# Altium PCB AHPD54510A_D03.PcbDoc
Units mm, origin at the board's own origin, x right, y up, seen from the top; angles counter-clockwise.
Board outline 70.4 x 70.4 mm, 2 copper layers (Top Layer, Bottom Layer), stack 1.57 mm thick; 18 components, 11 nets, 73 pads, 316 vias.
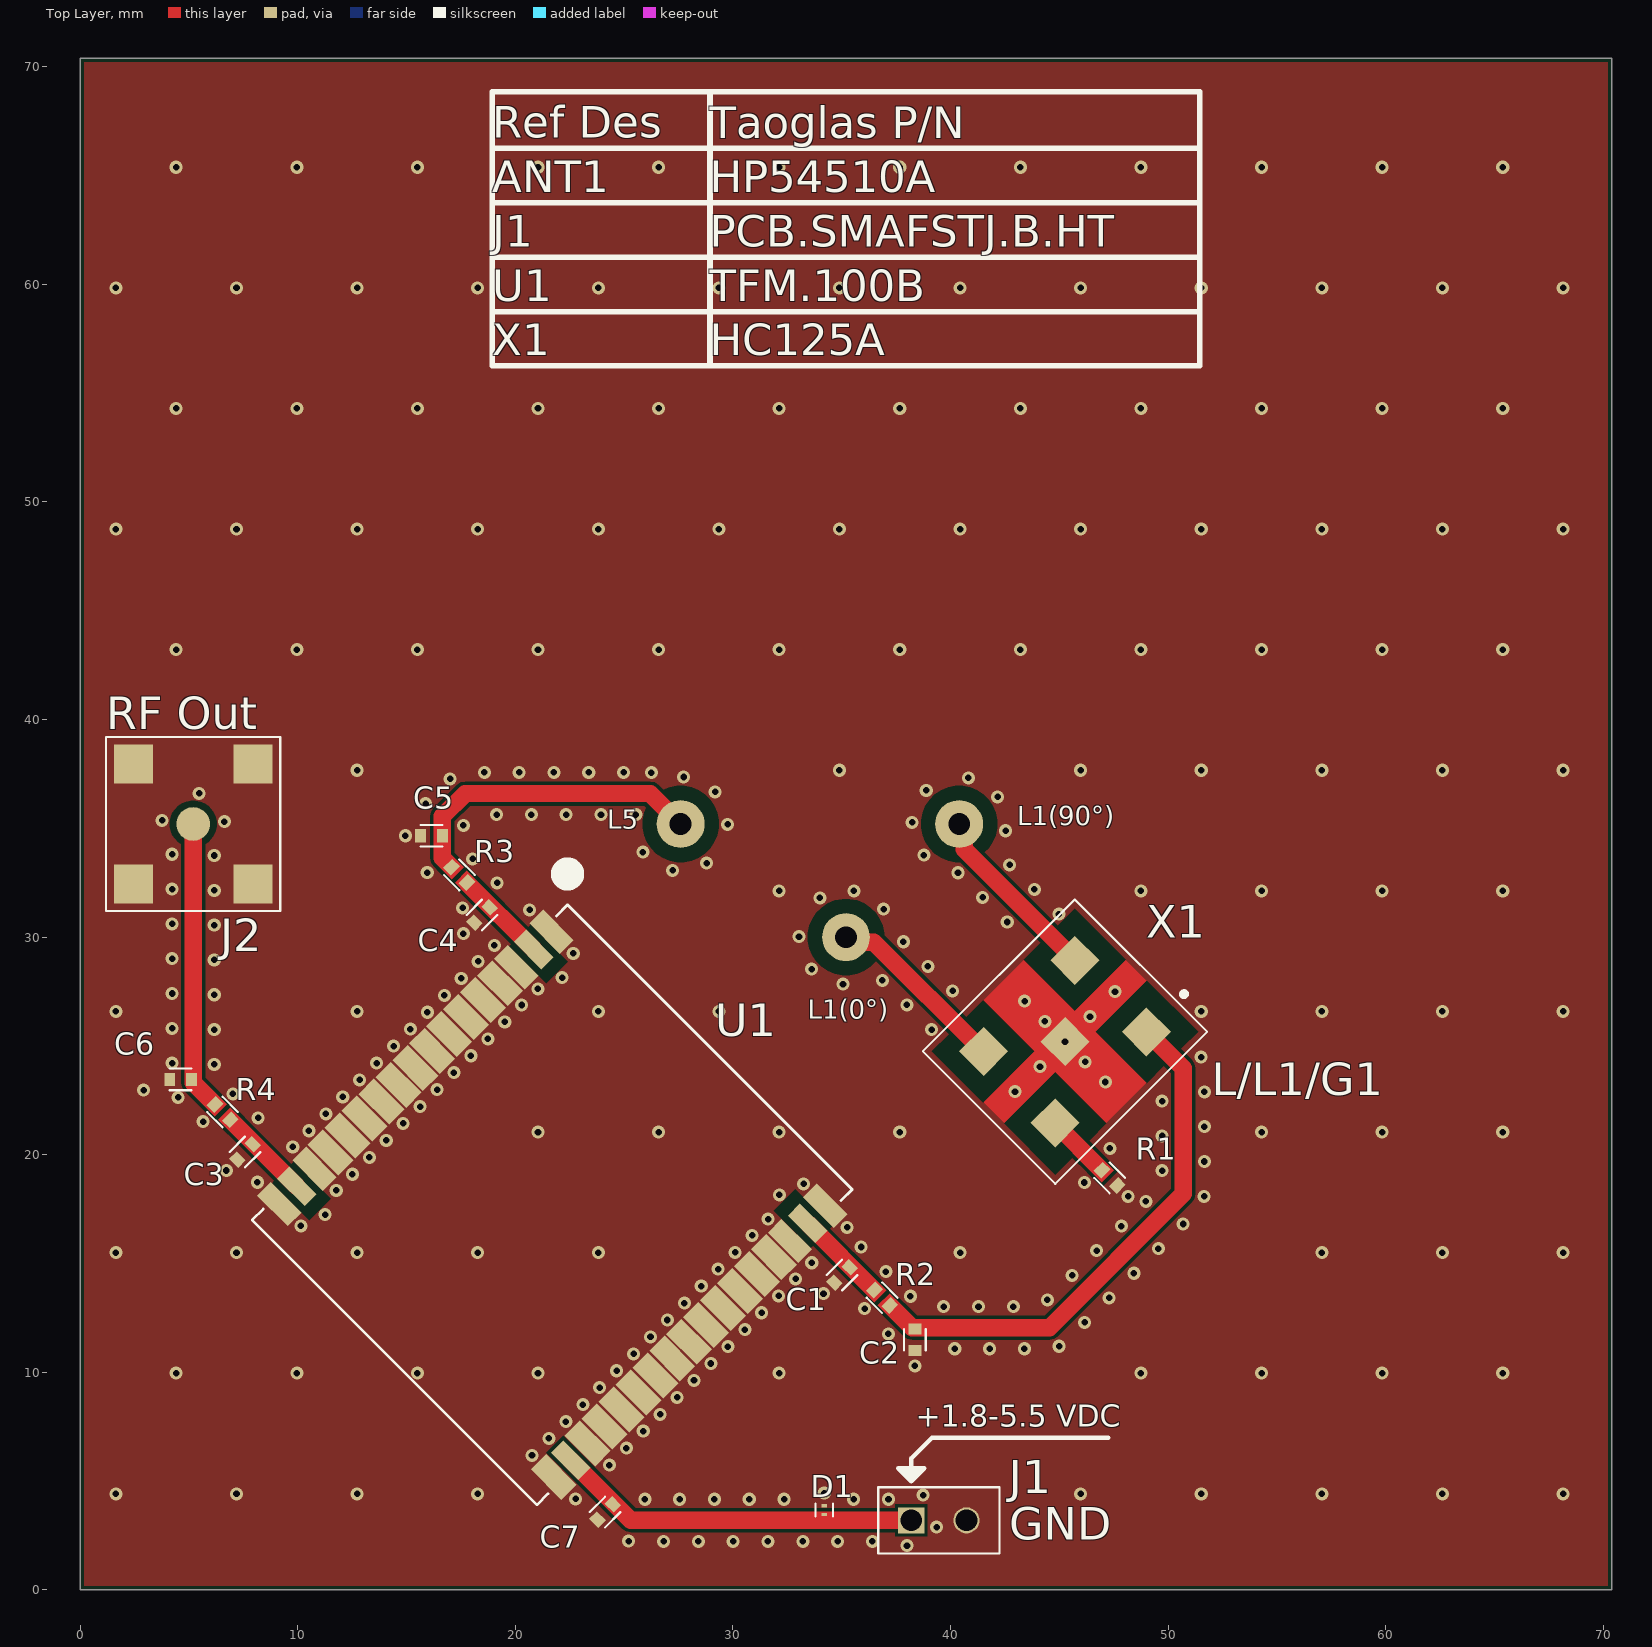
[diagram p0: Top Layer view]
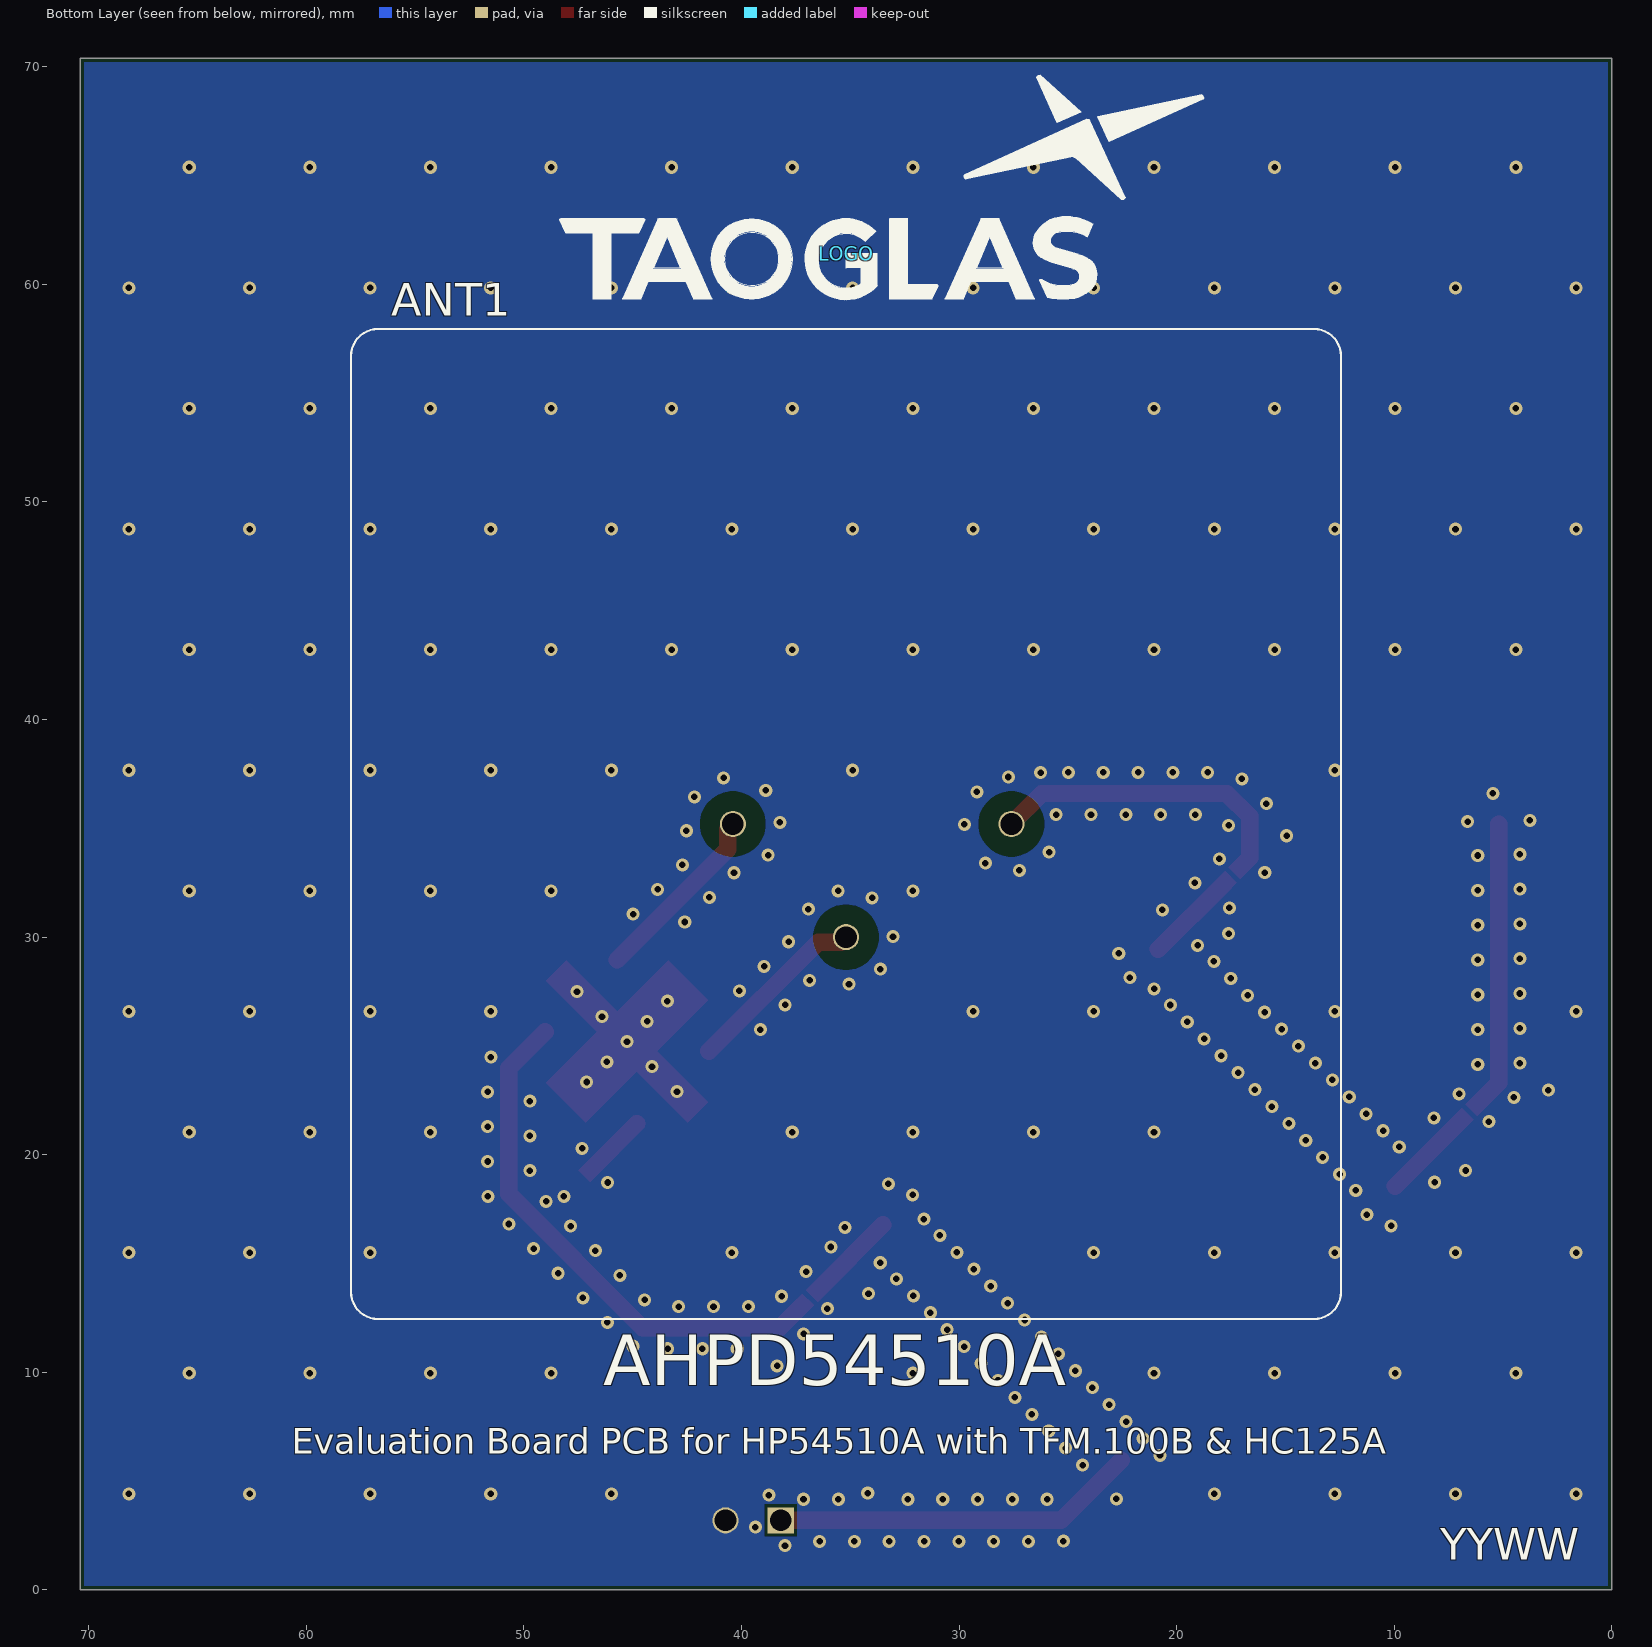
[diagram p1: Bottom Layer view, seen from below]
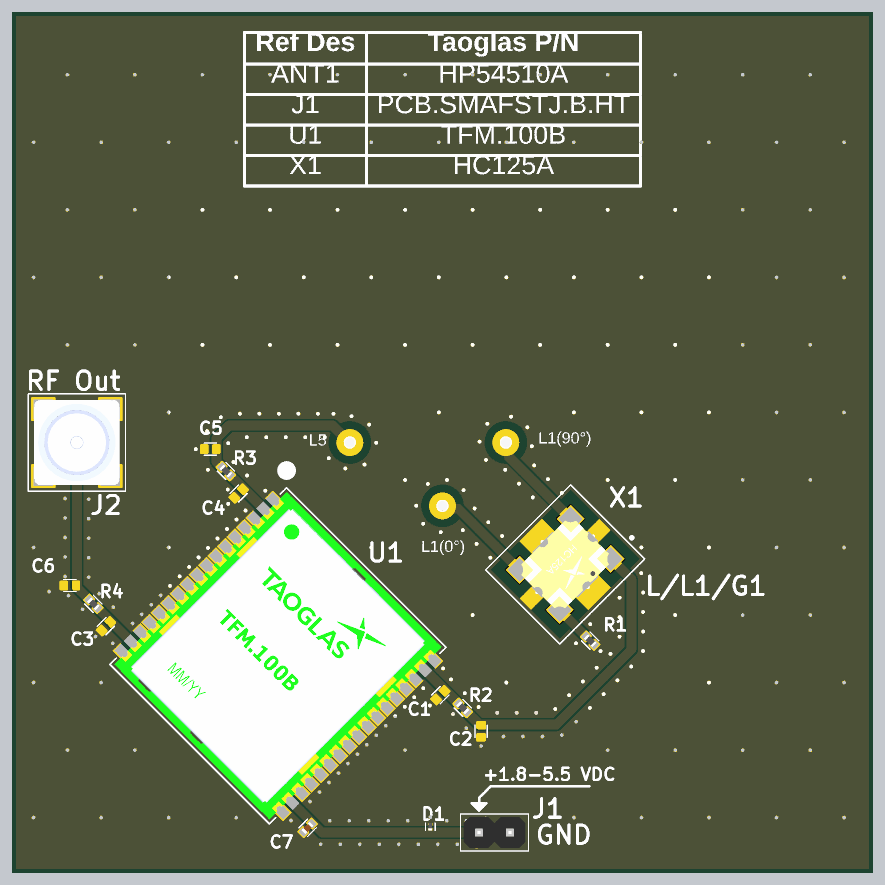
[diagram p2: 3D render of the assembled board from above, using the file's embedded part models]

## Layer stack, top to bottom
Top Solder Mask: solder mask 0.01, Solder Resist, Dk 3.5
Top Layer: signal copper 0.035
Dielectric: core 1.5, FR-4, Dk 4.2
Bottom Layer: signal copper 0.035
Bottom Solder Mask: solder mask 0.01, Solder Resist, Dk 3.5

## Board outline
0,0 70.4,0 70.4,70.4 0,70.4

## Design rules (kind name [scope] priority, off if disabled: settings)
BoardOutlineClearance [All] p1: gap=0.196 ignorepadtopadclearanceinfootprint=FALSE
Clearance Clearance_Polygon [All] p1: gap=0.14 ignorepadtopadclearanceinfootprint=FALSE except(0.05: Arc-Arc Arc-Track Track-Track; 0.1: Arc-SMDPad Arc-THPad Track-SMDPad Track-THPad SMDPad-SMDPad SMDPad-THPad THPad-THPad; 0.2: Arc-Via Arc-Text Arc-Hole Track-Via Track-Text Track-Hole SMDPad-Via SMDPad-Text SMDPad-Hole THPad-Via THPad-Text THPad-Hole Via-Via Via-Text Via-Hole Fill-Text Fill-Hole Poly-Text Poly-Hole Region-Text Region-Hole Text-Text Text-Hole)
HoleSize [All] p1: absolutevalues=TRUE maxlimit=6 minlimit=0.15 maxpercent=80.000 minpercent=20.000
MinimumAnnularRing [All] p1: minimumring=0.1
MinimumSolderMaskSliver [All vs InPadClass('All Pads')] p1: minsoldermaskwidth=0.05
PolygonConnect [All] p1: connectstyle=Direct reliefconductorwidth=0.254 reliefentries=4 polygonreliefangle="90 Angle" airgapwidth=0.254
RoutingVias [All] p1: holewidth=0.3 width=0.8 viastyle="Through Hole" minholewidth=0.15 minwidth=0.65 maxholewidth=6 maxwidth=6.5
SilkToSilkClearance [All] p1: silktosilkclearance=0.1
SilkToSolderMaskClearance [IsPad or IsVia vs OnLayer('Top Overlay')] p1: minsilkscreentomaskgap=0.05 clearancetoexposedcopper=FALSE
SilkToSolderMaskClearance SilkToSolderMaskClearance_1 [IsPad or IsVia vs OnLayer('Bottom Overlay')] p2: minsilkscreentomaskgap=0.05 clearancetoexposedcopper=FALSE
SolderMaskExpansion [Not IsVia] p1: expansion=0.1 istentingtop=FALSE
Width [All] p1: maxlimit=5 minlimit=0.1 preferedwidth=1 minimp=50.000000 maximp=50.000000 favimp=50.000000
26 further rules are at their usual default settings.

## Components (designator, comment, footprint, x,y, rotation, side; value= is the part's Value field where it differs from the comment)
ANT1 "TAOGLAS_HP54510A" TAOGLAS_HP54510A 35.2,35.2 r180 bottom
C1 "DNF" "0402 - DNF" 35.019,14.473 r225 top
C2 "DNF" "0402 - DNF" 38.368,11.499 r90 top
C3 "DNF" "0402 - DNF" 7.583,20.13 r45 top
C4 "DNF" "0402 - DNF" 18.473,31.019 r45 top
C5 "DNF" "0402 - DNF" 16.15,34.66 r180 top
C6 "DNF" "0402 - DNF" 4.623,23.467 r180 top
C7 "Capacitor_Ceramic_1005(0402)_L1_W0.5_H0.5mm_100pF+-5%_50V_-55 to 125C_Murata_GRM1555C1H101JA01" "Capacitor - 0402 - GRM" 24.13,3.583 r45 top value=100pF
D1 "ESD245B1W0201E6327XTSA1" "Diode - 0201 (0603 Metric) - DSN0603-2" 34.2,3.67 r90 top
J1 "PREC002SAAN-RC" SULLINS_PREC002SAAN-RC 39.47,3.2 r0 top
J2 "TAOGLAS_PCB.SMAFSTJ.B.HT" TAOGLAS_PCB.SMAFSTJ.B.HT 5.2,35.2 r90 top
LOGO "TAOGLAS_LOGO" "TAOGLAS_LOGO - No R - 10.3mm" 35.2,61.4 r180 bottom
R1 "Resistor_Thick Film_1005(0402)_49.9Ohms+-1%_0.1W" "Resistor - 0402 - ERJ-2RK" 47.315,18.937 r315 top value=49.9
R2 "Resistor_Thick Film_1005(0402)_0Ohm" "Resistor - 0402 - RC_L" 36.861,13.428 r315 top value=0
R3 "Resistor_Thick Film_1005(0402)_0Ohm" "Resistor - 0402 - RC_L" 17.428,32.861 r135 top value=0
R4 "Resistor_Thick Film_1005(0402)_0Ohm" "Resistor - 0402 - RC_L" 6.552,21.959 r315 top value=0
U1 "TAOGLAS_TFM.100B" TAOGLAS_TFM.100B 21.7,17.7 r315 top
X1 "TAOGLAS_HC125A" TAOGLAS_HC125A 45.264,25.2 r225 top

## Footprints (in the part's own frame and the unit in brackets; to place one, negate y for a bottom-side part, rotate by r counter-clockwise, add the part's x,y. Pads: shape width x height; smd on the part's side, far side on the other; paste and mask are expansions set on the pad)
"0402 - DNF" [mm]
  rect 0.5x0.6 smd paste-2539.97 mask+0.1: 1(-0.5,0) 2(0.5,0)
  silkscreen extent -0.5,-0.5 0.5,0.5
"Capacitor - 0402 - GRM" [mm]
  rect 0.5x0.6 smd mask+0.1: 1(-0.5,0) 2(0.5,0)
  silkscreen extent -0.5,-0.5 0.5,0.5, body extent -0.5,-0.25 0.5,0.25, height 0.55
"Diode - 0201 (0603 Metric) - DSN0603-2" [mm]
  rect 0.14x0.24 smd paste-2539.97 mask+0.05: 1(-0.2,0) 2(0.2,0)
  silkscreen extent -0.3,-0.4 0.3,0.4, body extent -0.3,-0.15 0.3,0.15, height 0.32
"Resistor - 0402 - ERJ-2RK" [mm]
  rect 0.5x0.6 smd mask+0.1: 1(-0.5,0) 2(0.5,0)
  silkscreen extent -0.5,-0.5 0.5,0.5, body extent -0.5,-0.25 0.5,0.25, height 0.35
"Resistor - 0402 - RC_L" [mm]
  rect 0.5x0.6 smd mask+0.1: 1(-0.5,0) 2(0.5,0)
  silkscreen extent -0.5,-0.5 0.5,0.5, body extent -0.5,-0.25 0.5,0.25, height 0.4
SULLINS_PREC002SAAN-RC [mm] "2 Positions Header, 0.100\" (2.54mm)"
  rect 1.2x1.2 hole 1 mask+0.1: 1(-1.27,0)
  round 1.2 hole 1 mask+0.1: 2(1.27,0)
  silkscreen extent -2.79,-1.52 2.79,2.12, body extent -2.54,-1.27 2.54,1.27, height 8.38
TAOGLAS_HC125A [mm] "Low Profile, High Performance Multiband GNSS Hybrid Coupler"
  rect 1.6x1.6 smd paste-0.1 mask+0.1: 1(-2.96,2.325) 2(2.96,2.325) 3(2.96,-2.325) 4(-2.96,-2.325)
  rect 1.6x1.6 smd: 5(0,0)
  Top Layer region: -4.62,0.665 -4.62,-0.665 -1.3,-0.665 -1.3,-3.985 1.3,-3.985 1.3,-0.665 4.62,-0.665 4.62,0.665 1.3,0.665 1.3,3.985 -1.3,3.985 -1.3,0.665
  silkscreen extent -5.51,-4.3 4.94,4.3, body extent -3.17,-2.54 3.18,2.54, height 1.5
TAOGLAS_HP54510A [mm] "Passive Multiband High Precision GNSS L1/L5 Stacked Patch Antenna"
  round 1.2 / inner round 2.2 / far side round 2.2 hole 1 paste-0.1: 1(0,-5.2) 2(-5.2,0) 3(7.6,0)
  Bottom Layer pour cut-out: 7.6,-1.747 8.27,-1.614 8.837,-1.235 9.217,-0.667 9.35,0.003 9.35,0.003 9.35,0.003 9.217,0.672 8.837,1.24 8.27,1.619 7.6,1.753 7.6,1.753 6.93,1.619 6.363,1.24 5.983,0.672 5.85,0.003 5.85,0.003 5.85,0.003 5.983,-0.667 6.363,-1.235 6.93,-1.614 7.6,-1.747
  Bottom Layer pour cut-out: -5.2,-1.747 -4.53,-1.614 -3.963,-1.235 -3.583,-0.667 -3.45,0.003 -3.45,0.003 -3.45,0.003 -3.583,0.672 -3.963,1.24 -4.53,1.619 -5.2,1.753 -5.2,1.753 -5.87,1.619 -6.437,1.24 -6.817,0.672 -6.95,0.003 -6.95,0.003 -6.95,0.003 -6.817,-0.667 -6.437,-1.235 -5.87,-1.614 -5.2,-1.747
  Bottom Layer pour cut-out: 0,-6.947 0.67,-6.814 1.237,-6.435 1.617,-5.867 1.75,-5.197 1.75,-5.197 1.75,-5.197 1.617,-4.528 1.237,-3.96 0.67,-3.581 0,-3.447 0,-3.447 -0.67,-3.581 -1.237,-3.96 -1.617,-4.528 -1.75,-5.197 -1.75,-5.197 -1.75,-5.197 -1.617,-5.867 -1.237,-6.435 -0.67,-6.814 0,-6.947
  Multi-Layer pour cut-out: 6.1,0 6.214,-0.574 6.539,-1.061 7.026,-1.386 7.6,-1.5 7.6,-1.5 8.174,-1.386 8.661,-1.061 8.986,-0.574 9.1,0 9.1,0 8.986,0.574 8.661,1.061 8.174,1.386 7.6,1.5 7.6,1.5 7.026,1.386 6.539,1.061 6.214,0.574 6.1,0
  Multi-Layer pour cut-out: -6.7,0 -6.586,-0.574 -6.261,-1.061 -5.774,-1.386 -5.2,-1.5 -5.2,-1.5 -4.626,-1.386 -4.139,-1.061 -3.814,-0.574 -3.7,0 -3.7,0 -3.814,0.574 -4.139,1.061 -4.626,1.386 -5.2,1.5 -5.2,1.5 -5.774,1.386 -6.261,1.061 -6.586,0.574 -6.7,0
  Multi-Layer pour cut-out: -1.5,-5.2 -1.386,-5.774 -1.061,-6.261 -0.574,-6.586 0,-6.7 0,-6.7 0.574,-6.586 1.061,-6.261 1.386,-5.774 1.5,-5.2 1.5,-5.2 1.386,-4.626 1.061,-4.139 0.574,-3.814 0,-3.7 0,-3.7 -0.574,-3.814 -1.061,-4.139 -1.386,-4.626 -1.5,-5.2
  silkscreen extent -22.75,-22.75 22.75,22.75, body extent -22.5,-22.5 22.5,22.5, height 10.2
"TAOGLAS_LOGO - No R - 10.3mm" [mm] "Total Height from bottom of the text to the top of the star is 10.3mm"
  silkscreen extent -13.15,-2.12 16.43,8.2
TAOGLAS_PCB.SMAFSTJ.B.HT [mm] "SMA (F) Surface Mount PCB Jack"
  round 1.55 smd paste-0.1 mask+0.1: 1(0,0)
  rect 1.8x1.8 smd paste-0.1 mask+0.1: 2(-2.75,2.75) 3(2.75,2.75) 4(-2.75,-2.75) 5(2.75,-2.75)
  silkscreen extent -4,-4 4,4, body extent -3.5,-3.5 3.5,3.5, height 10.23
TAOGLAS_TFM.100B [mm] "Surface mount GNSS front-end module covering L1/L5"
  rect 2x0.9 smd paste-2539.97 mask+0: 1(-8.9,8.85) 3(-8.9,6.55) 15(-8.9,-6.55) 17(-8.9,-8.85) 32(8.9,6.55) 34(8.9,8.85)
  rect 1.8x0.8 smd paste-2539.97: 2(-8.9,7.7) 16(-8.9,-7.7) 19(8.9,-7.7) 33(8.9,7.7)
  rect 2x1 smd paste-2539.97 mask+0: 4(-8.9,5.5) 5(-8.9,4.4) 6(-8.9,3.3) 7(-8.9,2.2) 8(-8.9,1.1) 9(-8.9,0) 10(-8.9,-1.1) 11(-8.9,-2.2) 12(-8.9,-3.3) 13(-8.9,-4.4) 14(-8.9,-5.5) 18(8.9,-8.8) 20(8.9,-6.6) 21(8.9,-5.5) 22(8.9,-4.4) 23(8.9,-3.3) 24(8.9,-2.2) 25(8.9,-1.1) 26(8.9,0) 27(8.9,1.1) 28(8.9,2.2) 29(8.9,3.3) 30(8.9,4.4) 31(8.9,5.5)
  silkscreen extent -10.5,-10.25 9.25,11.5, body extent -9,-10 9,10, height 2.74

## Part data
ANT1: library part CMP-270-000002-3, "Passive Multiband High Precision GNSS L1/L5 Stacked Patch Antenna", Temp_High=+85C, Temp_Low=-40C
C1 C2 C3 C4 C5 C6: library part CMP-00006-25, "Do Not Fit"
C7: library part CMP-001-00343-45, "100 pF ±5% 50V Ceramic Capacitor C0G, NP0 0402 (1005 Metric)", Max. Operating Temperature=125°C, Min. Operating Temperature=-55°C, Package / Case="0402 (1005 Metric)", Temperature Coefficient="C0G, NP0", Tolerance=±5%, Voltage - Rated=50V
D1: library part CMP-004-00167-10, "7.5V Clamp 5.5A (8/20µs) Ipp Tvs Diode Surface Mount WLL-2-3", Capacitance @ Frequency="5.8pF @ 1GHz", Current - Peak Pulse (10/1000µs)="5.5A (8/20µs)", Max. Operating Temperature=125°C, Max. Voltage - Clamping @ Ipp=7.5V, Min. Operating Temperature=-55°C, Package / Case="0201 (0603 Metric)", Power - Peak Pulse=44W, Power Line Protection=No, Supplier Device Package=WLL-2-3, Voltage - Reverse Standoff (Typ)=5.5V
J1: library part CMP-002-00180-7, "Connector Header Through Hole 2 position 0.100\" (2.54mm)", Temp_High=105°C, Temp_Low=-40°C
J2: library part CMP-028-000009-10, "SMA (F) Surface Mount PCB Jack", Temp_High=+85C, Temp_Low=-40C
LOGO: library part CMP-048-000000-3, "Silkscreen Logo - Standard"
R1: library part CMP-009-00256-10, "49.9 Ohms ±1% 0.1W, 1/10W Chip Resistor 0402 (1005 Metric) Automotive AEC-Q200 Thick Film", Max. Operating Temperature=155°C, Min. Operating Temperature=-25°C, Package / Case="0402 (1005 Metric)", Power (Watts)=100mW, Temperature Coefficient=±100ppm/°C, Tolerance=±1%
R2 R3 R4: library part CMP-009-00375-4, "0 Ohms Jumper Chip Resistor 0402 (1005 Metric) Moisture Resistant Thick Film", Max. Operating Temperature=155°C, Min. Operating Temperature=-55°C, Package / Case="0402 (1005 Metric)"
U1: library part CMP-266-000001-10, "Surface mount GNSS front-end module covering L1/L5", Temp_High=+85C, Temp_Low=-40C
X1: library part CMP-002-000151-19, "Low Profile, High Performance Multiband GNSS Hybrid Coupler", Center Frequency=1.39GHz

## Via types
v1: diameter 0.6, hole 0.3, Top Layer to Bottom Layer, tented both sides, 316 vias

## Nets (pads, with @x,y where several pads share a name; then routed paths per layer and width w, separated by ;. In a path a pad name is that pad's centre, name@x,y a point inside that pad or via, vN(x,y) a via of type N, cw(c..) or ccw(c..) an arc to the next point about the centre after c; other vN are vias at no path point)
GND: C1.2 C2.1 C3.1 C4.1 C5.2 C6.2 C7.1 D1.2 J1.2 J2.2 J2.3 J2.4 J2.5 R1.2 U1.1 U1.3 U1.4 U1.5 U1.6 U1.7 U1.8 U1.9 U1.10 U1.11 U1.12 U1.13 U1.14 U1.15 U1.17 U1.18 U1.20 U1.21 U1.22 U1.23 U1.24 U1.25 U1.26 U1.27 U1.28 U1.29 U1.30 U1.31 U1.32 U1.34 X1.5
  other v1: 38.003,2.039 26.814,2.231 28.414,2.231 30.014,2.231 31.614,2.231 33.214,2.231 34.814,2.231 36.414,2.231 25.215,2.242 39.361,2.886 22.771,4.184 25.953,4.169 27.553,4.169 29.153,4.169 30.753,4.169 32.353,4.169 35.553,4.169 37.153,4.169 38.741,4.361 1.648,4.419 7.19,4.419 12.732,4.419 18.274,4.419 45.984,4.419 51.526,4.419 57.068,4.419 62.61,4.419 68.152,4.419 34.2,4.455 24.326,5.74 20.771,6.184 25.104,6.518 21.549,6.962 25.882,7.295 22.326,7.74 26.66,8.073 23.104,8.518 27.438,8.851 23.882,9.295 28.215,9.629 4.419,9.961 9.961,9.961 15.503,9.961 21.045,9.961 32.129,9.961 48.755,9.961 54.297,9.961 59.839,9.961 65.381,9.961 24.66,10.073 38.368,10.299 28.993,10.407 25.438,10.851 40.198,11.084 41.798,11.084 43.398,11.084 29.771,11.185 44.994,11.199 26.215,11.629 37.152,11.768 30.549,11.962 46.162,12.292 26.993,12.407 31.327,12.74 36.055,12.933 39.689,13.021 41.289,13.021 42.889,13.021 27.771,13.185 44.459,13.329 47.294,13.424 38.162,13.498 32.105,13.518 34.166,13.619 28.549,13.962 32.882,14.296 45.59,14.46 48.425,14.555 37.03,14.629 29.327,14.74 33.625,15.038 1.648,15.503 7.19,15.503 12.732,15.503 18.274,15.503 23.816,15.503 30.105,15.518 40.442,15.503 57.068,15.503 62.61,15.503 68.152,15.503 46.722,15.592 49.556,15.686 35.899,15.76 30.882,16.296 35.251,16.665 10.149,16.735 47.853,16.723 50.688,16.818 31.625,17.038 11.262,17.249 48.985,17.854 48.169,18.084 51.658,18.09 32.138,18.151 11.775,18.362 33.251,18.665 8.149,18.735 46.158,18.725 12.518,19.104 6.73,19.276 49.731,19.269 51.669,19.69 13.295,19.882 47.329,20.294 9.775,20.362 14.073,20.66 49.731,20.869 21.045,21.045 26.587,21.045 32.129,21.045 37.671,21.045 54.297,21.045 59.839,21.045 65.381,21.045 10.518,21.104 51.669,21.29 14.851,21.438 5.656,21.519 8.184,21.697 11.295,21.882 15.629,22.215 49.731,22.469 4.509,22.635 12.073,22.66 7.027,22.802 42.966,22.902 51.669,22.89 2.923,22.967 16.407,22.993 47.12,23.344 12.851,23.438 17.185,23.771 44.115,24.051 6.169,24.152 4.231,24.211 13.629,24.215 46.192,24.272 51.516,24.483 17.962,24.549 14.407,24.993 45.264,25.2 18.74,25.327 6.169,25.752 39.131,25.752 15.185,25.771 4.231,25.811 19.518,26.105 44.336,26.128 46.413,26.349 15.962,26.549 1.648,26.587 12.732,26.587 23.816,26.587 29.358,26.587 51.526,26.587 57.068,26.587 62.61,26.587 68.152,26.587 20.296,26.882 38,26.883 43.408,27.056 16.74,27.327 6.169,27.352 4.231,27.411 47.562,27.498 40.095,27.527 21.038,27.625 35.063,27.841 36.869,28.014 17.518,28.105 22.151,28.138 33.618,28.528 38.964,28.659 18.296,28.882 6.169,28.952 4.231,29.011 22.665,29.251 19.038,29.625 37.833,29.79 33.041,30.02 17.619,30.166 6.169,30.552 4.231,30.611 42.61,30.696 44.986,31.06 20.665,31.251 36.93,31.292 17.578,31.342 34.001,31.801 41.479,31.827 32.129,32.129 35.566,32.129 48.755,32.129 54.297,32.129 59.839,32.129 65.381,32.129 6.169,32.152 43.855,32.191 4.231,32.211 19.164,32.496 15.955,32.969 40.347,32.959 27.234,33.071 42.723,33.322 28.799,33.399 18.045,33.599 6.169,33.752 38.776,33.77 4.231,33.811 25.87,33.908 14.95,34.66 42.537,34.89 17.619,35.141 29.759,35.18 38.241,35.278 6.633,35.31 3.775,35.371 19.142,35.631 20.742,35.631 22.342,35.631 23.942,35.631 25.542,35.631 15.884,36.133 42.165,36.447 5.476,36.611 29.182,36.672 38.887,36.741 17.005,37.274 40.825,37.322 27.737,37.359 18.577,37.569 20.177,37.569 21.777,37.569 23.377,37.569 24.977,37.569 26.254,37.558 12.732,37.671 34.9,37.671 45.984,37.671 51.526,37.671 57.068,37.671 62.61,37.671 68.152,37.671 4.419,43.213 9.961,43.213 15.503,43.213 21.045,43.213 26.587,43.213 32.129,43.213 37.671,43.213 43.213,43.213 48.755,43.213 54.297,43.213 59.839,43.213 65.381,43.213 1.648,48.755 7.19,48.755 12.732,48.755 18.274,48.755 23.816,48.755 29.358,48.755 34.9,48.755 40.442,48.755 45.984,48.755 51.526,48.755 57.068,48.755 62.61,48.755 68.152,48.755 4.419,54.297 9.961,54.297 15.503,54.297 21.045,54.297 26.587,54.297 32.129,54.297 37.671,54.297 43.213,54.297 48.755,54.297 54.297,54.297 59.839,54.297 65.381,54.297 1.648,59.839 7.19,59.839 12.732,59.839 18.274,59.839 23.816,59.839 29.358,59.839 34.9,59.839 40.442,59.839 45.984,59.839 51.526,59.839 57.068,59.839 62.61,59.839 68.152,59.839 4.419,65.381 9.961,65.381 15.503,65.381 21.045,65.381 26.587,65.381 32.129,65.381 37.671,65.381 43.213,65.381 48.755,65.381 54.297,65.381 59.839,65.381 65.381,65.381
NetANT1_1: ANT1.1 X1.3 | length 8.5
  Top Layer w0.8: ANT1.1 35.43,29.77 36.482,29.77 X1.3@41.502,24.751
NetANT1_2: ANT1.2 X1.4 | length 8.4
  Top Layer w0.8: ANT1.2 40.63,34.97 40.63,34.046 X1.4@45.713,28.963
NetANT1_3: ANT1.3 C5.1 R3.2 | length 14.6
  Top Layer w0.8: R3.2 16.65,33.639 16.65,34.731 C5.1 16.65,35.55 17.7,36.6 26.2,36.6 ANT1.3
NetC1_1: C1.1 R2.1 U1.33 | length 4.2
  Top Layer w0.8: U1.33@33.509,16.781 R2.1
NetC2_2: C2.2 R2.2 X1.1 | length 24.6
  Top Layer w0.8: R2.2 38.237,12.053 38.368,12.053 44.553,12.053 50.7,18.2 50.7,23.975 X1.1@49.026,25.649
NetC3_2: C3.2 R4.2 U1.16 | length 4.3
  Top Layer w0.8: R4.2 U1.16
NetC4_2: C4.2 R3.1 U1.2 | length 4.3
  Top Layer w0.8: R3.1 U1.2
NetC6_1: C6.1 J2.1 R4.1 | length 13.3
  Top Layer w0.8: J2.1 5.2,23.311 R4.1
NetC7_2: C7.2 D1.1 J1.1 U1.19 | length 16.8
  Top Layer w0.8: U1.19 25.311,3.2 30.2,3.2 J1.1
NetR1_1: R1.1 X1.2 | length 3
  Top Layer w0.8: X1.2@44.815,21.437 R1.1

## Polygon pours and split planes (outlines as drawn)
GND on Bottom Layer "GND_L02_P000" (solid, remove dead copper, pour order 1): 0,0 70.4,0 70.4,70.4 0,70.4
GND on Top Layer "GND_L01_P000" (solid, remove dead copper, pour order 0): 0,0 70.4,0 70.4,70.4 0,70.4

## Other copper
Top Layer:
  region net NetR1_1: 46.962,18.725 47.527,19.291 46.962,19.857 46.396,19.291
  region net NetANT1_3: 17.075,32.649 17.64,33.215 17.075,33.781 16.509,33.215
  region net NetC4_2: 17.782,31.942 18.347,32.508 17.782,33.074 17.216,32.508
  region net NetC3_2: 6.905,21.039 7.471,21.605 6.906,22.171 6.34,21.605
  region net NetC6_1: 6.198,21.746 6.764,22.312 6.198,22.878 5.633,22.312
  region net NetC1_1: 36.508,13.216 37.074,13.782 36.508,14.347 35.942,13.782
  region net NetC2_2: 37.215,12.509 37.781,13.075 37.215,13.64 36.649,13.075
  pour cut-out: 4.125,35.2 ccw(c5.2,35.2) 5.2,34.125 ccw(c5.2,35.2) 6.275,35.2 ccw(c5.2,35.2) 5.2,36.275 ccw(c5.2,35.2) 4.125,35.2
  pour cut-out: 6.091,21.639 6.871,22.419 7.013,22.278 6.233,21.498
  pour cut-out: 16.967,32.542 17.747,33.322 17.889,33.181 17.109,32.401
  pour cut-out: 36.401,13.109 37.181,13.889 37.322,13.747 36.542,12.967
  pour cut-out: 46.855,18.618 47.635,19.398 47.742,19.291 46.962,18.511
  pour cut-out: 21.424,6.308 22.202,7.087 22.938,6.351 22.159,5.573
  pour cut-out: 31.882,17.417 32.872,18.407 34.569,16.71 33.579,15.72
  pour cut-out: 8.831,18.69 9.821,19.68 11.518,17.983 10.528,16.993
  pour cut-out: 19.72,29.579 20.71,30.569 22.407,28.872 21.417,27.882
  pour cut-out: 44.815,23.789 47.167,21.438 44.815,19.086 42.463,21.437
  pour cut-out: 41.502,27.102 43.854,24.751 41.502,22.399 39.15,24.751
  pour cut-out: 45.714,31.314 48.065,28.963 45.713,26.611 43.362,28.962
  pour cut-out: 49.027,28.001 51.378,25.649 49.027,23.298 46.675,25.649
  text ".Layer_Name" at -44.35,55.034 h2
Bottom Layer:
  text ".Layer_Name" at -44.35,50.034 h2

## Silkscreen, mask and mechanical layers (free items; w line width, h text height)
Top Overlay:
  rectangle: 37.793,5.331 38.604,5.659
  rectangle: 37.965,5.155 38.418,5.439
  region: 195.173,23.762 195.173,24.215
  lines w0.2: 38.2,5.086 38.2,6.048 39.149,6.997 47.251,6.997 ; 37.603,5.597 38.2,5 38.797,5.597 37.603,5.597
  lines w0.254: 18.95,58.75 51.45,58.75 ; 18.95,61.25 51.45,61.25 ; 18.95,63.75 51.45,63.75 ; 18.95,66.25 51.45,66.25 ; 28.95,56.25 28.95,68.85 ; 18.95,56.25 51.45,56.25 51.45,68.85 18.95,68.85 18.95,56.25
  text "Ref Des" at 18.95,66.25 h2.5
  text "Taoglas P/N" at 28.95,66.229 h2.5
  text "ANT1" at 18.95,63.75 h2.5
  text "HP54510A" at 28.95,63.75 h2.5
  text "J1" at 18.95,61.25 h2.5
  text "PCB.SMAFSTJ.B.HT" at 28.95,61.25 h2.5
  text "U1" at 18.95,58.75 h2.5
  text "TFM.100B" at 28.95,58.75 h2.5
  text "X1" at 18.95,56.25 h2.5
  text "HC125A" at 28.95,56.25 h2.5
  text ".Layer_Name" at -44.35,45.034 h2
  text "RF Out" at 1.201,39.55 h1.5
  text "L1(90°)" at 43.066,34.853 h1.5
  text "L5" at 24.23,34.678 h1.5
  text "L1(0°)" at 33.439,25.953 h1.5
  text "L/L1/G1" at 51.998,22.724 h1.5
  text "+1.8-5.5 VDC" at 38.402,7.5 h1
  text "GND" at 42.7,2.3 h1.5
Bottom Overlay:
  text ".Layer_Name" at -44.35,40.034 h2
  text "AHPD54510A" at 46.353,8.635 h4
  text "Evaluation Board PCB for HP54510A with TFM.100B & HC125A" at 60.667,5.862 h2
  text "YYWW" at 7.898,0.9 h2.5
Top Paste:
  text ".Layer_Name" at -44.35,25.034 h2
Bottom Paste:
  text ".Layer_Name" at -44.35,19.7 h2
Top Solder Mask:
  text ".Layer_Name" at -44.35,35.034 h2
Bottom Solder Mask:
  text ".Layer_Name" at -44.35,29.7 h2
Board Outline:
  the board outline again, w0.254
  text ".Layer_Name" at -44.35,59.7 h2
Top Assembly:
  text ".Layer_Name" at -44.35,15.034 h2
Bottom Assembly:
  text ".Layer_Name" at -44.35,10.034 h2
IDW (Mech7):
  drawing of 191 lines, arcs and shapes, not listed
  text "Layer" at -27.113,-13.554 h1.52
  text "Name" at -16.702,-13.554 h1.52
  text "Material" at 12.754,-13.554 h1.52
  text "Thickness" at 34.592,-13.554 h1.52
  text "Constant" at 51.098,-13.554 h1.52
  text "Board Layer Stack" at 65.572,-13.554 h1.52
  text "Top Overlay" at -16.702,-16.602 h1.52
  text "Top Solder Mask" at -16.702,-19.65 h1.52
  text "Solder Resist" at 12.754,-19.65 h1.52
  text "0.010mm" at 34.592,-19.65 h1.52
  text "3.5" at 51.098,-19.65 h1.52
  text "1" at -27.113,-22.698 h1.52
  text "Top Layer" at -16.702,-22.698 h1.52
  text "0.035mm" at 34.592,-22.698 h1.52
  text "Dielectric" at -16.702,-25.746 h1.52
  text "FR-4" at 12.754,-25.746 h1.52
  text "1.500mm" at 34.592,-25.746 h1.52
  text "4.2" at 51.098,-25.746 h1.52
  text "2" at -27.113,-28.794 h1.52
  text "Bottom Layer" at -16.702,-28.794 h1.52
  text "0.035mm" at 34.592,-28.794 h1.52
  text "Bottom Solder Mask" at -16.702,-31.842 h1.52
  text "Solder Resist" at 12.754,-31.842 h1.52
  text "0.010mm" at 34.592,-31.842 h1.52
  text "3.5" at 51.098,-31.842 h1.52
  text "Bottom Overlay" at -16.702,-34.89 h1.52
